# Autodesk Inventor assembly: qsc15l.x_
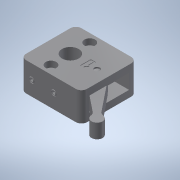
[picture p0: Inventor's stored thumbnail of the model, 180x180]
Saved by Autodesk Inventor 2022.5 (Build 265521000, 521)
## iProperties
Part Number: qsc15l.x_
Material: 一般
Document SubType Name: Assembly
Designer: ImaoCorp
Sending System: SOLIDWORKS 2017-2017317
MC: AMD64
MC_MODEL: Intel64 Family 6 Model 60 Stepping 3, GenuineIntel
OS: Windows_NT
FRU: Parasolid Version 29.0, build 201,  4-17-2017
FORMAT: text
GUISE: transmit
KEY: qsc15l
FILE: qsc15l.x_t
DATE: Wed Sep 04 15:35:35 2019
Author: ImaoCorp
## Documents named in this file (7)
- X:\14_SW2022-Inv2022\00_全2023-1023新製品(TCC)まで\q\qsc15l\QSC15L.iam
- X:\14_SW2022-Inv2022\00_全2023-1023新製品(TCC)まで\q\qsc15l\qsc15l_01.ipt
- X:\14_SW2022-Inv2022\00_全2023-1023新製品(TCC)まで\q\qsc15l\qsc15l_02.ipt
- X:\14_SW2022-Inv2022\00_全2023-1023新製品(TCC)まで\q\qsc15l\qsc15l_03.ipt
- X:\14_SW2022-Inv2022\00_全2023-1023新製品(TCC)まで\q\qsc15l\qsc15l_04.ipt
- X:\14_SW2022-Inv2022\00_全2023-1023新製品(TCC)まで\q\qsc15l\qsc15l_05.ipt
- X:\14_SW2022-Inv2022\00_全2023-1023新製品(TCC)まで\q\qsc15l\qsc15l_06.ipt
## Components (6 placed, 6 different names)
1. qsc15l_01
2. qsc15l_02
3. qsc15l_03
4. qsc15l_04
5. qsc15l_05
6. qsc15l_06
